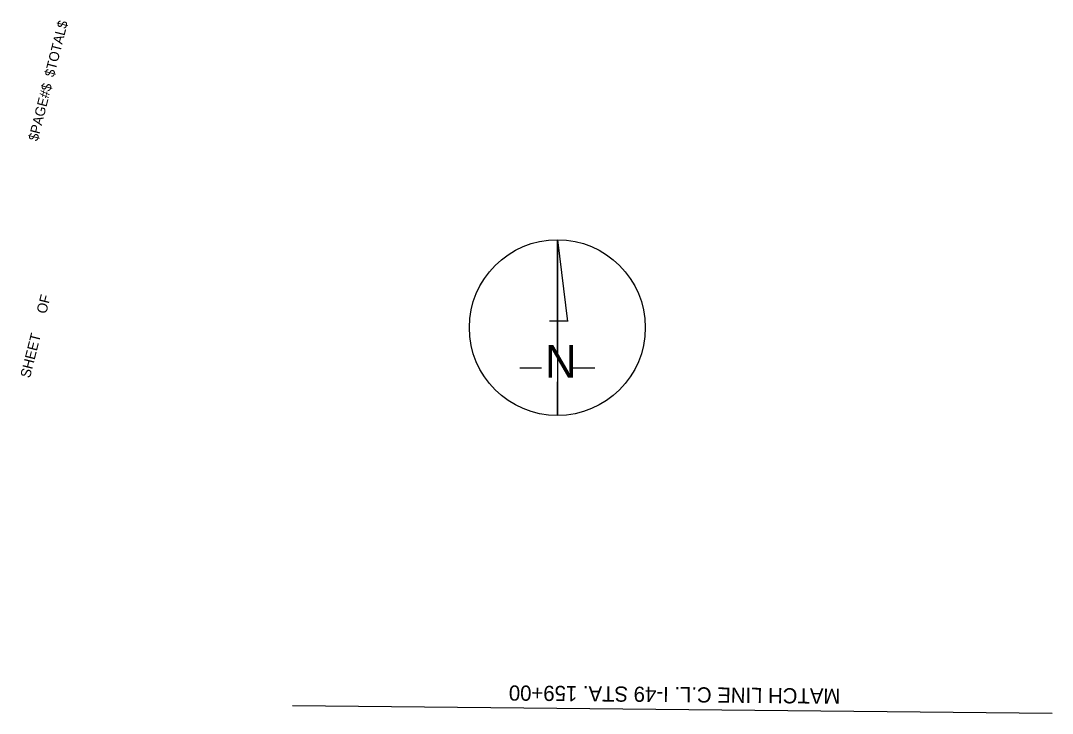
# Model space of a CAD drawing. Extents: x 631240 to 632657, y 370244 to 373550.
import ezdxf

# ---------------------------------------------------------------- set-up
doc = ezdxf.new("R2010")
doc.units = 0
for name, color, linetype in [('Copy of R_Dimension', 7, 'Continuous'), ('R_Border_N Arrow', 7, 'Continuous'), ('R_Draft', 7, 'Continuous'), ('S_DITCHLINE', 7, 'Continuous')]:
    doc.layers.add(name, color=color, linetype=linetype)

msp = doc.modelspace()

# ---------------------------------------------------------------- linework, layer by layer
at = {"layer": 'Copy of R_Dimension'}
msp.add_line((632070.9, 373290), (632070.9, 373081.7), dxfattribs=at)
msp.add_circle((632070.9, 373185.9), 104.2, dxfattribs=at)
at = {"layer": 'R_Border_N Arrow'}
for p, q in [((632070.9, 373290), (632083, 373193)), ((632070.9, 373154.4), (632070.9, 373290)), ((632061.5, 373193.8), (632083.1, 373193.8)), ((632026.3, 373138.4), (632052, 373138.4)), ((632088, 373138.4), (632115.5, 373138.4)), ((632070.9, 373081.7), (632070.9, 373121.6))]:
    msp.add_line(p, q, dxfattribs=at)
at = {"layer": 'R_Draft'}
msp.add_line((632657.2, 372728.8), (631757.3, 372737.8), dxfattribs=at)

# ---------------------------------------------------------------- texts
at = {"layer": 'Copy of R_Dimension'}
for s, p in [('OF', (631465.4, 373201.6)), ('SHEET', (631446.2, 373125.5))]:
    msp.add_text(s, height=12, rotation=75.7827, dxfattribs=at).set_placement(p)
at = {"layer": 'R_Border_N Arrow'}
msp.add_text('N', height=38.8, dxfattribs=at).set_placement((632056.2, 373126.5))
at = {"layer": 'R_Draft'}
for s, p in [('$TOTAL$', (631474.6, 373482.1)), ('$PAGE#$', (631455.4, 373406.2))]:
    msp.add_text(s, height=11.72, rotation=75.7827, dxfattribs=at).set_placement(p)
at = {"layer": 'S_DITCHLINE'}
msp.add_text('MATCH LINE C.L. I-49 STA. 159+00', height=18, rotation=179.4304, dxfattribs=at).set_placement((632406.2, 372758.1))

doc.saveas('drawing.dxf')
